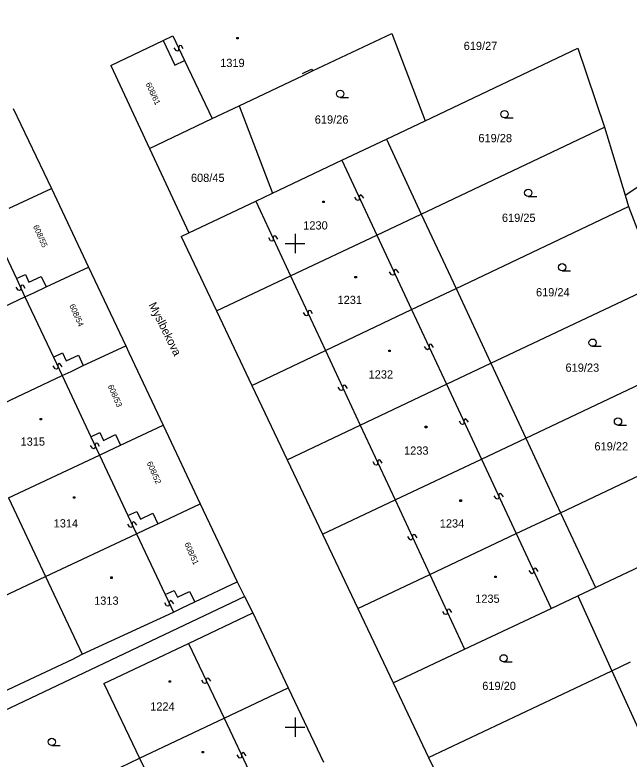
# Model space of a CAD drawing. Extents: x -493648 to -493033, y -1127718 to -1127026.
# Drawn here: x -493128.9 to -493065.5, y -1127103.3 to -1127026.4 of the extents above; entities that cross this region are included whole.
import ezdxf

# ---------------------------------------------------------------- set-up
doc = ezdxf.new("R2010")
doc.units = 0
doc.layers.add('katastrální mapa', color=7, linetype='Continuous')
doc.layers.add('síť', color=7, linetype='Continuous')

msp = doc.modelspace()

# ---------------------------------------------------------------- linework, layer by layer
at = {"layer": 'katastrální mapa'}
for p, q in [((-493065.9, -1127045.01), (-493037.66, -1127026.38)), ((-493113.62, -1127029.04), (-493112.62, -1127028.56)), ((-493112.62, -1127028.56), (-493111.41, -1127031.1)), ((-493098.19, -1127032.17), (-493090.01, -1127028.3)), ((-493090.01, -1127028.3), (-493086.55, -1127037.32)), ((-493119.03, -1127031.62), (-493113.62, -1127029.04)), ((-493113.62, -1127029.04), (-493112.42, -1127031.57)), ((-493106.02, -1127028.7), (-493105.87, -1127028.7)), ((-493106.02, -1127028.85), (-493106.02, -1127028.7)), ((-493105.87, -1127028.85), (-493106.02, -1127028.85)), ((-493105.87, -1127028.7), (-493105.87, -1127028.85)), ((-493112.29, -1127030.07), (-493112.48, -1127029.78)), ((-493112.15, -1127030.12), (-493112.29, -1127030.07)), ((-493112.06, -1127030.08), (-493112.15, -1127030.12)), ((-493112.02, -1127029.94), (-493112.06, -1127030.08)), ((-493112.01, -1127029.72), (-493112.02, -1127029.94)), ((-493111.97, -1127029.58), (-493112.01, -1127029.72)), ((-493111.88, -1127029.54), (-493111.97, -1127029.58)), ((-493111.74, -1127029.59), (-493111.88, -1127029.54)), ((-493111.55, -1127029.88), (-493111.74, -1127029.59)), ((-493086.55, -1127037.32), (-493070.78, -1127029.83)), ((-493070.78, -1127029.83), (-493068.02, -1127037.98)), ((-493119.03, -1127031.62), (-493115.02, -1127040.18)), ((-493112.42, -1127031.57), (-493111.41, -1127031.1)), ((-493111.41, -1127031.1), (-493108.55, -1127037.1)), ((-493099.23, -1127032.45), (-493098.28, -1127032)), ((-493099.15, -1127032.63), (-493098.19, -1127032.17)), ((-493098.28, -1127032), (-493098.19, -1127032.17)), ((-493105.78, -1127035.79), (-493099.15, -1127032.63)), ((-493095.34, -1127034.91), (-493094.46, -1127034.91)), ((-493129.11, -1127036.07), (-493125.16, -1127044.31)), ((-493108.55, -1127037.1), (-493105.78, -1127035.79)), ((-493105.78, -1127035.79), (-493102.33, -1127044.81)), ((-493078.36, -1127037.01), (-493077.48, -1127037.01)), ((-493115.02, -1127040.18), (-493108.55, -1127037.1)), ((-493090.56, -1127039.22), (-493086.55, -1127037.32)), ((-493086.96, -1127046.96), (-493068.02, -1127037.98)), ((-493068.02, -1127037.98), (-493065.9, -1127045.01)), ((-493095.17, -1127041.41), (-493090.56, -1127039.22)), ((-493090.56, -1127039.22), (-493086.96, -1127046.96)), ((-493115.02, -1127040.18), (-493110.95, -1127048.89)), ((-493102.33, -1127044.81), (-493095.17, -1127041.41)), ((-493095.17, -1127041.41), (-493091.56, -1127049.14)), ((-493129.54, -1127046.37), (-493125.16, -1127044.31)), ((-493125.16, -1127044.31), (-493121.33, -1127052.44)), ((-493104.05, -1127045.63), (-493102.33, -1127044.81)), ((-493093.64, -1127045.51), (-493093.83, -1127045.22)), ((-493093.51, -1127045.56), (-493093.64, -1127045.51)), ((-493093.42, -1127045.52), (-493093.51, -1127045.56)), ((-493093.37, -1127045.39), (-493093.42, -1127045.52)), ((-493093.36, -1127045.16), (-493093.37, -1127045.39)), ((-493093.31, -1127045.03), (-493093.36, -1127045.16)), ((-493093.22, -1127044.99), (-493093.31, -1127045.03)), ((-493093.09, -1127045.04), (-493093.22, -1127044.99)), ((-493092.9, -1127045.33), (-493093.09, -1127045.04)), ((-493075.91, -1127045.14), (-493075.03, -1127045.14)), ((-493065.9, -1127045.01), (-493065.54, -1127046.19)), ((-493110.95, -1127048.89), (-493104.05, -1127045.63)), ((-493104.05, -1127045.63), (-493100.45, -1127053.35)), ((-493097.14, -1127045.62), (-493096.99, -1127045.62)), ((-493097.14, -1127045.77), (-493097.14, -1127045.62)), ((-493096.99, -1127045.77), (-493097.14, -1127045.77)), ((-493096.99, -1127045.62), (-493096.99, -1127045.77)), ((-493083.37, -1127054.66), (-493065.54, -1127046.19)), ((-493065.54, -1127046.19), (-493062.51, -1127054.22)), ((-493091.56, -1127049.14), (-493086.96, -1127046.96)), ((-493086.96, -1127046.96), (-493083.37, -1127054.66)), ((-493131.72, -1127047.39), (-493128.77, -1127053.64)), ((-493111.76, -1127049.29), (-493110.95, -1127048.89)), ((-493111.76, -1127049.29), (-493108.11, -1127056.98)), ((-493102.2, -1127049.25), (-493102.25, -1127049.38)), ((-493102.25, -1127049.38), (-493102.25, -1127049.6)), ((-493102.11, -1127049.2), (-493102.2, -1127049.25)), ((-493101.98, -1127049.25), (-493102.11, -1127049.2)), ((-493101.78, -1127049.55), (-493101.98, -1127049.25)), ((-493100.45, -1127053.35), (-493091.56, -1127049.14)), ((-493091.56, -1127049.14), (-493087.96, -1127056.84)), ((-493102.52, -1127049.73), (-493102.72, -1127049.43)), ((-493102.39, -1127049.78), (-493102.52, -1127049.73)), ((-493102.3, -1127049.73), (-493102.39, -1127049.78)), ((-493102.25, -1127049.6), (-493102.3, -1127049.73)), ((-493125.71, -1127054.5), (-493121.33, -1127052.44)), ((-493121.33, -1127052.44), (-493117.49, -1127060.57)), ((-493128.77, -1127053.64), (-493127.85, -1127053.21)), ((-493127.85, -1127053.21), (-493127.48, -1127054.01)), ((-493090.03, -1127053.23), (-493090.23, -1127052.93)), ((-493089.9, -1127053.28), (-493090.03, -1127053.23)), ((-493089.81, -1127053.23), (-493089.9, -1127053.28)), ((-493089.76, -1127053.1), (-493089.81, -1127053.23)), ((-493089.71, -1127052.75), (-493089.76, -1127052.88)), ((-493089.76, -1127052.88), (-493089.76, -1127053.1)), ((-493089.62, -1127052.7), (-493089.71, -1127052.75)), ((-493089.49, -1127052.75), (-493089.62, -1127052.7)), ((-493089.29, -1127053.05), (-493089.49, -1127052.75)), ((-493072.41, -1127052.84), (-493071.53, -1127052.84)), ((-493128.77, -1127053.64), (-493127.89, -1127055.53)), ((-493127.48, -1127054.01), (-493126.22, -1127053.42)), ((-493126.22, -1127053.42), (-493125.71, -1127054.5)), ((-493108.11, -1127056.98), (-493100.45, -1127053.35)), ((-493100.45, -1127053.35), (-493096.86, -1127061.06)), ((-493093.81, -1127053.41), (-493093.66, -1127053.41)), ((-493093.81, -1127053.56), (-493093.81, -1127053.41)), ((-493093.66, -1127053.56), (-493093.81, -1127053.56)), ((-493093.66, -1127053.41), (-493093.66, -1127053.56)), ((-493128.61, -1127054.82), (-493128.8, -1127054.53)), ((-493128.33, -1127054.7), (-493128.38, -1127054.83)), ((-493128.28, -1127054.34), (-493128.33, -1127054.47)), ((-493128.33, -1127054.47), (-493128.33, -1127054.7)), ((-493128.19, -1127054.3), (-493128.28, -1127054.34)), ((-493128.05, -1127054.35), (-493128.19, -1127054.3)), ((-493127.86, -1127054.64), (-493128.05, -1127054.35)), ((-493126.98, -1127055.1), (-493125.71, -1127054.5)), ((-493087.96, -1127056.84), (-493083.37, -1127054.66)), ((-493083.37, -1127054.66), (-493079.77, -1127062.39)), ((-493079.77, -1127062.39), (-493062.51, -1127054.22)), ((-493137.27, -1127059.94), (-493127.89, -1127055.53)), ((-493128.47, -1127054.87), (-493128.61, -1127054.82)), ((-493128.38, -1127054.83), (-493128.47, -1127054.87)), ((-493127.89, -1127055.53), (-493126.98, -1127055.1)), ((-493127.89, -1127055.53), (-493124.96, -1127061.76)), ((-493108.11, -1127056.98), (-493104.46, -1127064.67)), ((-493098.65, -1127057.09), (-493098.66, -1127057.32)), ((-493098.6, -1127056.96), (-493098.65, -1127057.09)), ((-493098.51, -1127056.92), (-493098.6, -1127056.96)), ((-493098.38, -1127056.97), (-493098.51, -1127056.92)), ((-493098.19, -1127057.26), (-493098.38, -1127056.97)), ((-493096.86, -1127061.06), (-493087.96, -1127056.84)), ((-493087.96, -1127056.84), (-493084.36, -1127064.56)), ((-493098.93, -1127057.44), (-493099.12, -1127057.15)), ((-493098.8, -1127057.49), (-493098.93, -1127057.44)), ((-493098.71, -1127057.45), (-493098.8, -1127057.49)), ((-493098.66, -1127057.32), (-493098.71, -1127057.45)), ((-493121.87, -1127062.63), (-493117.49, -1127060.57)), ((-493117.49, -1127060.57), (-493117.15, -1127061.28)), ((-493086.43, -1127060.94), (-493086.63, -1127060.64)), ((-493086.16, -1127060.81), (-493086.21, -1127060.94)), ((-493086.11, -1127060.46), (-493086.16, -1127060.59)), ((-493086.16, -1127060.59), (-493086.16, -1127060.81)), ((-493086.02, -1127060.41), (-493086.11, -1127060.46)), ((-493085.89, -1127060.46), (-493086.02, -1127060.41)), ((-493085.69, -1127060.76), (-493085.89, -1127060.46)), ((-493069.26, -1127060.63), (-493068.38, -1127060.63)), ((-493124.96, -1127061.76), (-493124.03, -1127061.32)), ((-493124.03, -1127061.32), (-493123.65, -1127062.14)), ((-493123.65, -1127062.14), (-493122.38, -1127061.54)), ((-493122.38, -1127061.54), (-493121.87, -1127062.63)), ((-493117.15, -1127061.28), (-493113.62, -1127068.78)), ((-493104.46, -1127064.67), (-493096.86, -1127061.06)), ((-493096.86, -1127061.06), (-493093.26, -1127068.78)), ((-493090.31, -1127061.02), (-493090.16, -1127061.02)), ((-493090.31, -1127061.17), (-493090.31, -1127061.02)), ((-493090.16, -1127061.17), (-493090.31, -1127061.17)), ((-493090.16, -1127061.02), (-493090.16, -1127061.17)), ((-493086.3, -1127060.99), (-493086.43, -1127060.94)), ((-493086.21, -1127060.94), (-493086.3, -1127060.99)), ((-493124.96, -1127061.76), (-493124.06, -1127063.66)), ((-493124.46, -1127062.47), (-493124.51, -1127062.6)), ((-493124.37, -1127062.42), (-493124.46, -1127062.47)), ((-493124.24, -1127062.47), (-493124.37, -1127062.42)), ((-493124.04, -1127062.76), (-493124.24, -1127062.47)), ((-493084.36, -1127064.56), (-493079.77, -1127062.39)), ((-493079.77, -1127062.39), (-493076.17, -1127070.11)), ((-493076.17, -1127070.11), (-493059.75, -1127062.34)), ((-493124.78, -1127062.95), (-493124.98, -1127062.66)), ((-493124.65, -1127063), (-493124.78, -1127062.95)), ((-493124.56, -1127062.95), (-493124.65, -1127063)), ((-493124.51, -1127062.82), (-493124.56, -1127062.95)), ((-493124.51, -1127062.6), (-493124.51, -1127062.82)), ((-493124.06, -1127063.66), (-493123.12, -1127063.22)), ((-493123.12, -1127063.22), (-493121.87, -1127062.63)), ((-493133.45, -1127068.07), (-493124.06, -1127063.66)), ((-493124.06, -1127063.66), (-493121.09, -1127069.98)), ((-493104.46, -1127064.67), (-493100.81, -1127072.35)), ((-493095.01, -1127064.68), (-493095.06, -1127064.81)), ((-493094.92, -1127064.63), (-493095.01, -1127064.68)), ((-493094.79, -1127064.68), (-493094.92, -1127064.63)), ((-493094.59, -1127064.98), (-493094.79, -1127064.68)), ((-493093.26, -1127068.78), (-493084.36, -1127064.56)), ((-493084.36, -1127064.56), (-493080.75, -1127072.28)), ((-493095.33, -1127065.16), (-493095.53, -1127064.86)), ((-493095.2, -1127065.21), (-493095.33, -1127065.16)), ((-493095.11, -1127065.16), (-493095.2, -1127065.21)), ((-493095.06, -1127065.03), (-493095.11, -1127065.16)), ((-493095.06, -1127064.81), (-493095.06, -1127065.03)), ((-493126.33, -1127068.09), (-493126.18, -1127068.09)), ((-493126.33, -1127068.24), (-493126.33, -1127068.09)), ((-493126.18, -1127068.24), (-493126.33, -1127068.24)), ((-493126.18, -1127068.09), (-493126.18, -1127068.24)), ((-493082.83, -1127068.66), (-493083.02, -1127068.36)), ((-493082.56, -1127068.53), (-493082.61, -1127068.66)), ((-493082.55, -1127068.31), (-493082.56, -1127068.53)), ((-493082.5, -1127068.18), (-493082.55, -1127068.31)), ((-493082.41, -1127068.13), (-493082.5, -1127068.18)), ((-493082.28, -1127068.18), (-493082.41, -1127068.13)), ((-493082.09, -1127068.48), (-493082.28, -1127068.18)), ((-493118.02, -1127070.85), (-493113.62, -1127068.78)), ((-493113.62, -1127068.78), (-493109.79, -1127076.9)), ((-493100.81, -1127072.35), (-493093.26, -1127068.78)), ((-493093.26, -1127068.78), (-493089.67, -1127076.5)), ((-493086.55, -1127068.89), (-493086.4, -1127068.89)), ((-493086.55, -1127069.04), (-493086.55, -1127068.89)), ((-493086.4, -1127069.04), (-493086.55, -1127069.04)), ((-493086.4, -1127068.89), (-493086.4, -1127069.04)), ((-493082.7, -1127068.71), (-493082.83, -1127068.66)), ((-493082.61, -1127068.66), (-493082.7, -1127068.71)), ((-493066.64, -1127068.77), (-493065.76, -1127068.77)), ((-493121.09, -1127069.98), (-493120.17, -1127069.54)), ((-493121.09, -1127069.98), (-493120.2, -1127071.87)), ((-493120.17, -1127069.54), (-493119.79, -1127070.35)), ((-493119.79, -1127070.35), (-493118.53, -1127069.76)), ((-493118.53, -1127069.76), (-493118.02, -1127070.85)), ((-493080.75, -1127072.28), (-493076.17, -1127070.11)), ((-493076.17, -1127070.11), (-493072.58, -1127077.83)), ((-493120.92, -1127071.16), (-493121.11, -1127070.87)), ((-493120.64, -1127070.81), (-493120.65, -1127071.04)), ((-493120.59, -1127070.68), (-493120.64, -1127070.81)), ((-493120.5, -1127070.64), (-493120.59, -1127070.68)), ((-493120.37, -1127070.69), (-493120.5, -1127070.64)), ((-493120.18, -1127070.98), (-493120.37, -1127070.69)), ((-493119.28, -1127071.44), (-493118.02, -1127070.85)), ((-493072.58, -1127077.83), (-493056.53, -1127070.24)), ((-493120.79, -1127071.21), (-493120.92, -1127071.16)), ((-493120.7, -1127071.17), (-493120.79, -1127071.21)), ((-493120.65, -1127071.04), (-493120.7, -1127071.17)), ((-493120.2, -1127071.87), (-493119.28, -1127071.44)), ((-493129.58, -1127076.28), (-493120.2, -1127071.87)), ((-493120.2, -1127071.87), (-493117.26, -1127078.12)), ((-493100.81, -1127072.35), (-493097.15, -1127080.04)), ((-493091.41, -1127072.4), (-493091.46, -1127072.53)), ((-493091.32, -1127072.35), (-493091.41, -1127072.4)), ((-493091.19, -1127072.4), (-493091.32, -1127072.35)), ((-493091, -1127072.7), (-493091.19, -1127072.4)), ((-493089.67, -1127076.5), (-493080.75, -1127072.28)), ((-493080.75, -1127072.28), (-493077.15, -1127079.99)), ((-493091.74, -1127072.88), (-493091.93, -1127072.58)), ((-493091.61, -1127072.93), (-493091.74, -1127072.88)), ((-493091.52, -1127072.88), (-493091.61, -1127072.93)), ((-493091.47, -1127072.75), (-493091.52, -1127072.88)), ((-493091.46, -1127072.53), (-493091.47, -1127072.75)), ((-493129.58, -1127076.28), (-493125.76, -1127084.43)), ((-493122.88, -1127076.19), (-493122.73, -1127076.19)), ((-493122.88, -1127076.34), (-493122.88, -1127076.19)), ((-493122.73, -1127076.19), (-493122.73, -1127076.34)), ((-493079.22, -1127076.37), (-493079.42, -1127076.08)), ((-493078.95, -1127076.25), (-493079, -1127076.38)), ((-493078.9, -1127075.89), (-493078.95, -1127076.02)), ((-493078.95, -1127076.02), (-493078.95, -1127076.25)), ((-493078.81, -1127075.85), (-493078.9, -1127075.89)), ((-493078.68, -1127075.9), (-493078.81, -1127075.85)), ((-493078.48, -1127076.19), (-493078.68, -1127075.9)), ((-493122.73, -1127076.34), (-493122.88, -1127076.34)), ((-493114.17, -1127078.97), (-493109.79, -1127076.9)), ((-493109.79, -1127076.9), (-493105.96, -1127084.98)), ((-493097.15, -1127080.04), (-493089.67, -1127076.5)), ((-493089.67, -1127076.5), (-493086.07, -1127084.22)), ((-493082.96, -1127076.51), (-493082.81, -1127076.51)), ((-493082.96, -1127076.66), (-493082.96, -1127076.51)), ((-493082.81, -1127076.66), (-493082.96, -1127076.66)), ((-493082.81, -1127076.51), (-493082.81, -1127076.66)), ((-493079.09, -1127076.42), (-493079.22, -1127076.37)), ((-493079, -1127076.38), (-493079.09, -1127076.42)), ((-493117.26, -1127078.12), (-493116.35, -1127077.69)), ((-493116.35, -1127077.69), (-493115.97, -1127078.5)), ((-493077.15, -1127079.99), (-493072.58, -1127077.83)), ((-493072.58, -1127077.83), (-493068.98, -1127085.55)), ((-493117.26, -1127078.12), (-493116.37, -1127080.01)), ((-493115.97, -1127078.5), (-493114.68, -1127077.89)), ((-493114.68, -1127077.89), (-493114.17, -1127078.97)), ((-493068.17, -1127085.17), (-493053.16, -1127078.07)), ((-493117.09, -1127079.3), (-493117.28, -1127079.01)), ((-493116.96, -1127079.35), (-493117.09, -1127079.3)), ((-493116.87, -1127079.31), (-493116.96, -1127079.35)), ((-493116.82, -1127079.18), (-493116.87, -1127079.31)), ((-493116.81, -1127078.95), (-493116.82, -1127079.18)), ((-493116.76, -1127078.82), (-493116.81, -1127078.95)), ((-493116.67, -1127078.78), (-493116.76, -1127078.82)), ((-493116.54, -1127078.83), (-493116.67, -1127078.78)), ((-493116.35, -1127079.12), (-493116.54, -1127078.83)), ((-493115.44, -1127079.57), (-493114.17, -1127078.97)), ((-493125.76, -1127084.43), (-493116.37, -1127080.01)), ((-493116.37, -1127080.01), (-493115.44, -1127079.57)), ((-493116.37, -1127080.01), (-493113.42, -1127086.28)), ((-493097.15, -1127080.04), (-493093.5, -1127087.73)), ((-493087.82, -1127080.12), (-493087.87, -1127080.25)), ((-493087.73, -1127080.07), (-493087.82, -1127080.12)), ((-493087.6, -1127080.12), (-493087.73, -1127080.07)), ((-493087.4, -1127080.42), (-493087.6, -1127080.12)), ((-493086.07, -1127084.22), (-493077.15, -1127079.99)), ((-493077.15, -1127079.99), (-493073.55, -1127087.71)), ((-493088.14, -1127080.6), (-493088.34, -1127080.3)), ((-493088.01, -1127080.65), (-493088.14, -1127080.6)), ((-493087.92, -1127080.6), (-493088.01, -1127080.65)), ((-493087.87, -1127080.47), (-493087.92, -1127080.6)), ((-493087.87, -1127080.25), (-493087.87, -1127080.47)), ((-493075.62, -1127084.09), (-493075.82, -1127083.79)), ((-493075.35, -1127083.96), (-493075.4, -1127084.09)), ((-493075.3, -1127083.61), (-493075.35, -1127083.74)), ((-493075.35, -1127083.74), (-493075.35, -1127083.96)), ((-493075.21, -1127083.56), (-493075.3, -1127083.61)), ((-493075.08, -1127083.61), (-493075.21, -1127083.56)), ((-493074.88, -1127083.91), (-493075.08, -1127083.61)), ((-493141.43, -1127091.81), (-493125.76, -1127084.43)), ((-493125.76, -1127084.43), (-493121.97, -1127092.46)), ((-493119.03, -1127084.47), (-493118.88, -1127084.47)), ((-493119.03, -1127084.62), (-493119.03, -1127084.47)), ((-493118.88, -1127084.62), (-493119.03, -1127084.62)), ((-493118.88, -1127084.47), (-493118.88, -1127084.62)), ((-493093.5, -1127087.73), (-493086.07, -1127084.22)), ((-493086.07, -1127084.22), (-493082.48, -1127091.93)), ((-493079.37, -1127084.38), (-493079.22, -1127084.38)), ((-493079.37, -1127084.53), (-493079.37, -1127084.38)), ((-493079.22, -1127084.53), (-493079.37, -1127084.53)), ((-493079.22, -1127084.38), (-493079.22, -1127084.53)), ((-493075.49, -1127084.14), (-493075.62, -1127084.09)), ((-493075.4, -1127084.09), (-493075.49, -1127084.14)), ((-493110.36, -1127087.05), (-493105.96, -1127084.98)), ((-493105.96, -1127084.98), (-493105.21, -1127086.48)), ((-493068.98, -1127085.55), (-493068.17, -1127085.17)), ((-493113.42, -1127086.28), (-493112.49, -1127085.85)), ((-493113.42, -1127086.28), (-493112.56, -1127088.12)), ((-493112.49, -1127085.85), (-493112.15, -1127086.57)), ((-493112.15, -1127086.57), (-493110.89, -1127085.97)), ((-493110.89, -1127085.97), (-493110.36, -1127087.05)), ((-493070.79, -1127086.41), (-493068.98, -1127085.55)), ((-493136.84, -1127101.5), (-493105.21, -1127086.48)), ((-493112.94, -1127086.96), (-493112.99, -1127087.09)), ((-493112.85, -1127086.91), (-493112.94, -1127086.96)), ((-493112.72, -1127086.96), (-493112.85, -1127086.91)), ((-493112.52, -1127087.26), (-493112.72, -1127086.96)), ((-493111.64, -1127087.65), (-493110.36, -1127087.05)), ((-493105.21, -1127086.48), (-493104.37, -1127088.18)), ((-493073.55, -1127087.71), (-493070.79, -1127086.41)), ((-493070.79, -1127086.41), (-493067.27, -1127094.16)), ((-493113.26, -1127087.44), (-493113.46, -1127087.14)), ((-493113.13, -1127087.49), (-493113.26, -1127087.44)), ((-493113.04, -1127087.44), (-493113.13, -1127087.49)), ((-493112.99, -1127087.31), (-493113.04, -1127087.44)), ((-493112.99, -1127087.09), (-493112.99, -1127087.31)), ((-493112.56, -1127088.12), (-493111.64, -1127087.65)), ((-493093.5, -1127087.73), (-493089.85, -1127095.42)), ((-493084.22, -1127087.83), (-493084.27, -1127087.96)), ((-493084.13, -1127087.79), (-493084.22, -1127087.83)), ((-493084, -1127087.84), (-493084.13, -1127087.79)), ((-493083.81, -1127088.13), (-493084, -1127087.84)), ((-493082.48, -1127091.93), (-493073.55, -1127087.71)), ((-493121.97, -1127092.46), (-493112.56, -1127088.12)), ((-493111.01, -1127091.33), (-493104.37, -1127088.18)), ((-493104.37, -1127088.18), (-493100.69, -1127095.92)), ((-493084.55, -1127088.31), (-493084.74, -1127088.02)), ((-493084.42, -1127088.36), (-493084.55, -1127088.31)), ((-493084.33, -1127088.32), (-493084.42, -1127088.36)), ((-493084.28, -1127088.19), (-493084.33, -1127088.32)), ((-493084.27, -1127087.96), (-493084.28, -1127088.19)), ((-493119.73, -1127095.47), (-493111.01, -1127091.33)), ((-493111.01, -1127091.33), (-493107.33, -1127099.07)), ((-493122.94, -1127092.96), (-493121.97, -1127092.46)), ((-493089.85, -1127095.42), (-493082.48, -1127091.93)), ((-493137.62, -1127099.85), (-493122.94, -1127092.96)), ((-493078.45, -1127093.25), (-493077.57, -1127093.25)), ((-493067.27, -1127094.16), (-493065.36, -1127093.25)), ((-493086.2, -1127103.11), (-493067.27, -1127094.16)), ((-493067.27, -1127094.16), (-493051.77, -1127128.35)), ((-493119.73, -1127095.47), (-493116.05, -1127103.21)), ((-493113.01, -1127095.19), (-493112.86, -1127095.19)), ((-493113.01, -1127095.34), (-493113.01, -1127095.19)), ((-493112.86, -1127095.34), (-493113.01, -1127095.34)), ((-493112.86, -1127095.19), (-493112.86, -1127095.34)), ((-493109.44, -1127095.44), (-493109.64, -1127095.15)), ((-493109.31, -1127095.49), (-493109.44, -1127095.44)), ((-493109.22, -1127095.45), (-493109.31, -1127095.49)), ((-493109.17, -1127095.31), (-493109.22, -1127095.45)), ((-493109.12, -1127094.95), (-493109.17, -1127095.09)), ((-493109.17, -1127095.09), (-493109.17, -1127095.31)), ((-493109.03, -1127094.91), (-493109.12, -1127094.95)), ((-493108.9, -1127094.96), (-493109.03, -1127094.91)), ((-493108.7, -1127095.25), (-493108.9, -1127094.96)), ((-493089.85, -1127095.42), (-493086.2, -1127103.11)), ((-493107.33, -1127099.07), (-493100.69, -1127095.92)), ((-493100.69, -1127095.92), (-493097.05, -1127103.6)), ((-493116.05, -1127103.21), (-493107.33, -1127099.07)), ((-493107.33, -1127099.07), (-493103.69, -1127106.75)), ((-493125.12, -1127101.89), (-493124.24, -1127101.89)), ((-493132.35, -1127110.95), (-493116.05, -1127103.21)), ((-493116.05, -1127103.21), (-493112.4, -1127110.89)), ((-493109.59, -1127102.51), (-493109.44, -1127102.51)), ((-493109.59, -1127102.66), (-493109.59, -1127102.51)), ((-493109.44, -1127102.66), (-493109.59, -1127102.66)), ((-493109.44, -1127102.51), (-493109.44, -1127102.66)), ((-493105.78, -1127103.15), (-493105.98, -1127102.86)), ((-493105.65, -1127103.2), (-493105.78, -1127103.15)), ((-493105.56, -1127103.15), (-493105.65, -1127103.2)), ((-493105.51, -1127103.02), (-493105.56, -1127103.15)), ((-493105.46, -1127102.67), (-493105.51, -1127102.8)), ((-493105.51, -1127102.8), (-493105.51, -1127103.02)), ((-493105.37, -1127102.62), (-493105.46, -1127102.67)), ((-493105.24, -1127102.67), (-493105.37, -1127102.62)), ((-493105.04, -1127102.96), (-493105.24, -1127102.67)), ((-493086.2, -1127103.11), (-493068.87, -1127139.58))]:
    msp.add_line(p, q, dxfattribs=at)
for centre in [(-493095.34, -1127034.535), (-493078.36, -1127036.635), (-493075.91, -1127044.765), (-493072.41, -1127052.465), (-493069.26, -1127060.255), (-493066.64, -1127068.395), (-493078.45, -1127092.875), (-493125.12, -1127101.515)]:
    msp.add_circle(centre, 0.375, dxfattribs=at)
at = {"layer": 'síť'}
for p, q in [((-493100, -1127049), (-493100, -1127051)), ((-493101, -1127050), (-493099, -1127050)), ((-493100, -1127099), (-493100, -1127101)), ((-493101, -1127100), (-493099, -1127100))]:
    msp.add_line(p, q, dxfattribs=at)

# ---------------------------------------------------------------- texts
at = {"layer": 'katastrální mapa'}
for s, p in [('619/27', (-493082.58, -1127030.01)), ('1319', (-493107.73, -1127031.77)), ('619/26', (-493097.96, -1127037.62)), ('619/28', (-493081.06, -1127039.54)), ('608/45', (-493110.75, -1127043.64)), ('619/25', (-493078.63, -1127047.77)), ('1230', (-493099.15, -1127048.56)), ('619/24', (-493075.11, -1127055.47)), ('1231', (-493095.61, -1127056.26)), ('619/23', (-493072.06, -1127063.26)), ('1232', (-493092.4, -1127063.96)), ('1315', (-493128.35, -1127070.9)), ('619/22', (-493069.07, -1127071.39)), ('1233', (-493088.74, -1127071.83)), ('1314', (-493124.93, -1127079.35)), ('1234', (-493085.05, -1127079.36)), ('1235', (-493081.39, -1127087.14)), ('1313', (-493120.75, -1127087.34)), ('619/20', (-493080.66, -1127096.15)), ('1224', (-493114.96, -1127098.28))]:
    msp.add_text(s, height=0.849996, dxfattribs=at).set_placement(p)
for s, height, rotation, p in [('608/61', 0.599994, 294.9569972, (-493115.45, -1127033.52)), ('608/55', 0.599994, 293.9849972, (-493127.07, -1127048.24)), ('608/54', 0.599994, 293.9849972, (-493123.33, -1127056.42)), ('Myslbekova', 0.849996, 296.559, (-493115.14, -1127056.34)), ('608/53', 0.599994, 293.9849972, (-493119.36, -1127064.74)), ('608/52', 0.599994, 293.9849972, (-493115.33, -1127072.69)), ('608/51', 0.599994, 293.9849972, (-493111.45, -1127081.04))]:
    msp.add_text(s, height=height, rotation=rotation, dxfattribs=at).set_placement(p)

doc.saveas('drawing.dxf')
